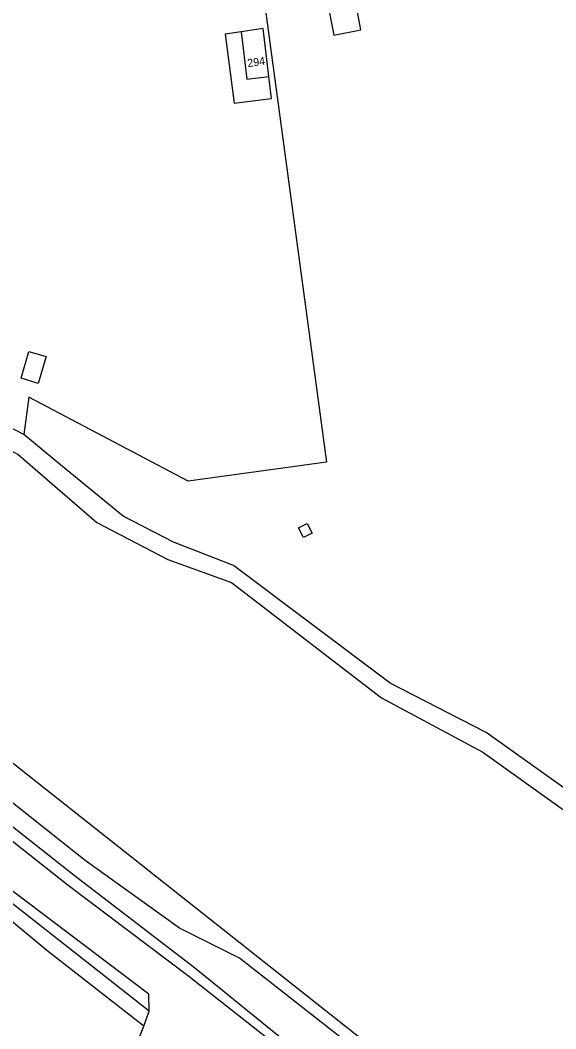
# Model space of a CAD drawing. Extents: x 124000 to 129000, y 395500 to 397503.
# Drawn here: x 128733.9 to 128800.9, y 395875.2 to 396001.2 of the extents above; entities that cross this region are included whole.
import ezdxf

# ---------------------------------------------------------------- set-up
doc = ezdxf.new("R2010")
doc.units = 0
for name, color, linetype in [('gg-afsc-draadraster', 7, 'Continuous'), ('gg-anno-huisnummerreeks BGT', 7, 'Continuous'), ('gg-bbg-bijgebouw', 7, 'Continuous'), ('gg-bbg-hoofdgebouw', 7, 'Continuous'), ('gg-bbg-luifel en loopbrug', 7, 'Continuous'), ('gg-knt-onverhard', 7, 'Continuous'), ('gg-kntw-greppel-droge sloot', 7, 'Continuous'), ('gt-grn-groengrens', 7, 'Continuous'), ('gt-grn-vlakafsluiter', 7, 'Continuous')]:
    doc.layers.add(name, color=color, linetype=linetype)

msp = doc.modelspace()

# ---------------------------------------------------------------- linework, layer by layer
at = {"layer": 'gg-afsc-draadraster'}
msp.add_line((128747.71, 395871.46), (128749.35, 395875.49), dxfattribs=at)
msp.add_lwpolyline([(128749.35, 395875.49), (128737.24, 395884.92), (128727.01, 395893.39)], dxfattribs=at)
at = {"layer": 'gg-bbg-bijgebouw'}
for points in [[(128775.69, 396004.23), (128772.3, 396003.57), (128773.14, 395999.29), (128776.52, 395999.95), (128775.69, 396004.23)], [(128736.16, 395955.79), (128734.01, 395956.42), (128734.99, 395959.78), (128737.14, 395959.15), (128736.16, 395955.79)], [(128768.71, 395937.76), (128769.78, 395938.3), (128770.41, 395937.06), (128769.34, 395936.52), (128768.71, 395937.76)]]:
    msp.add_lwpolyline(points, dxfattribs=at)
at = {"layer": 'gg-bbg-hoofdgebouw'}
for points in [[(128764.99, 395994.11), (128764.27, 396000.1), (128761.55, 395999.71)], [(128761.55, 395999.71), (128762.26, 395993.78), (128764.99, 395994.11)]]:
    msp.add_lwpolyline(points, dxfattribs=at)
at = {"layer": 'gg-bbg-luifel en loopbrug'}
msp.add_lwpolyline([(128761.55, 395999.71), (128759.54, 395999.43), (128760.65, 395990.77), (128765.34, 395991.38), (128764.99, 395994.11)], dxfattribs=at)
at = {"layer": 'gg-knt-onverhard'}
msp.add_line((128749.35, 395875.49), (128750.02, 395877.35), dxfattribs=at)
for points in [[(128814, 395999.34), (128823.27, 395979.39), (128822.78, 395972.92), (128820.06, 395952.27), (128820.83, 395945.07), (128821.14, 395934.21), (128820.22, 395926.05), (128818.49, 395919.38), (128814.26, 395912.6), (128808.22, 395908.83), (128802.17, 395905.07), (128792.17, 395912.18), (128780.18, 395918.34), (128760.57, 395933.04), (128753.09, 395935.93), (128746.76, 395939.19), (128739.2, 395945.42), (128734.35, 395949.41)], [(128954.35, 395760.78), (128948.98, 395764.44), (128925.7, 395777.97), (128910.15, 395787.23), (128877.36, 395803.24), (128864.3, 395808.96), (128847.57, 395816.53), (128832.35, 395823.92), (128813.92, 395836.35), (128802.82, 395844.06), (128782.88, 395859.45), (128770.3, 395869.66), (128754.99, 395881.7), (128739.9, 395893.06), (128722.48, 395906.81), (128714.46, 395913.11), (128696.72, 395926.81), (128676.46, 395942.51), (128659.09, 395956.88), (128648.97, 395968.49), (128642.86, 395979.71), (128637.73, 395993.56)], [(128709.55, 395962.19), (128708.38, 395959.94), (128733.59, 395946.96), (128743.49, 395938.39), (128752.36, 395933.79), (128760.31, 395930.91), (128779.07, 395916.49), (128791.78, 395909.7), (128802.14, 395902.3), (128814.83, 395909.02)], [(128734.35, 395949.41), (128717.98, 395957.85), (128709.55, 395962.19)], [(128750.02, 395877.35), (128749.97, 395879.49), (128721.22, 395901.18), (128719.69, 395899.22)]]:
    msp.add_lwpolyline(points, dxfattribs=at)
at = {"layer": 'gg-kntw-greppel-droge sloot'}
for points in [[(128789.27, 395862.1), (128761.33, 395884), (128753.83, 395887.71), (128742.03, 395896.17), (128724.2, 395910.31), (128696.36, 395932.6), (128678.44, 395946.53), (128667.84, 395954.51), (128654.86, 395965.03)], [(128770.35, 395870.89), (128755.7, 395882.78), (128740.64, 395894.3), (128722.62, 395908.52), (128695.05, 395930.42), (128676.59, 395944.87), (128666.59, 395952.95), (128658.64, 395958.92)], [(128750.02, 395877.35), (128724.84, 395897.11), (128723.87, 395895.89)]]:
    msp.add_lwpolyline(points, dxfattribs=at)
at = {"layer": 'gt-grn-groengrens'}
msp.add_line((128796.06, 395858.51), (128654.87, 395970.01), dxfattribs=at)
at = {"layer": 'gt-grn-vlakafsluiter'}
msp.add_lwpolyline([(128758.24, 396002.22), (128764.49, 396003), (128772.21, 395945.93), (128754.91, 395943.59), (128735, 395954.07), (128734.35, 395949.41)], dxfattribs=at)

# ---------------------------------------------------------------- texts
at = {"layer": 'gg-anno-huisnummerreeks BGT'}
msp.add_text('294', height=1, rotation=8, dxfattribs=at).set_placement((128762.38, 395995.29))

doc.saveas('drawing.dxf')
